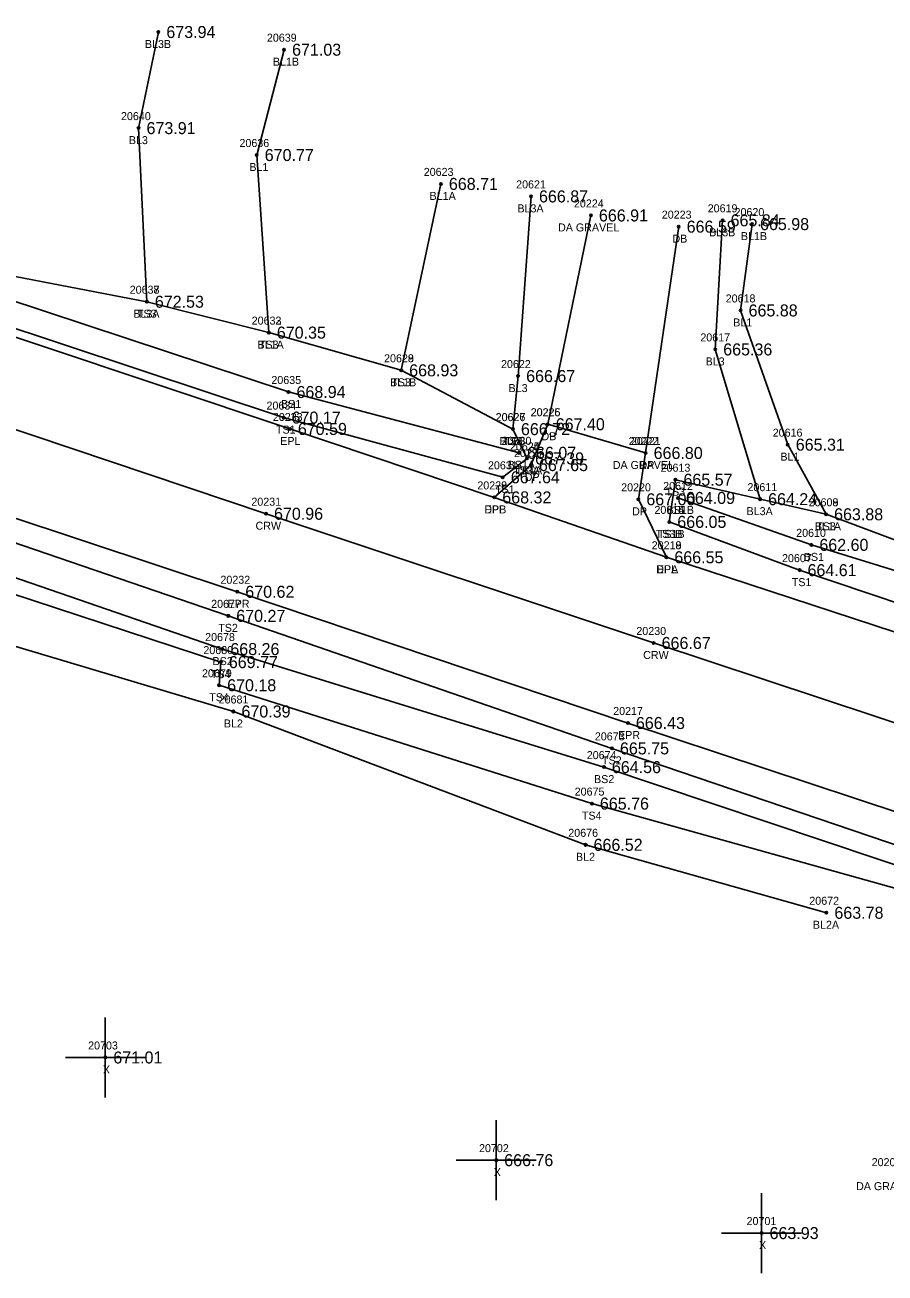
# Model space of a CAD drawing. Extents: x 1655675 to 1657082, y 1004080 to 1005193.
# Drawn here: x 1656108 to 1656215.6, y 1004608.6 to 1004764.5 of the extents above; entities that cross this region are included whole.
import ezdxf

# ---------------------------------------------------------------- set-up
doc = ezdxf.new("R2010")
doc.units = 0
for name, color, linetype in [('RD_DTM_BkLn1', 7, 'Continuous'), ('RD_DTM_BkLn2', 7, 'Continuous'), ('RD_DTM_BkLn_txCode', 7, 'Continuous'), ('RD_EX_Driveway', 7, 'Continuous'), ('RD_EX_Driveway_txCode', 7, 'Continuous'), ('RD_EX_Misc', 7, 'Continuous'), ('RD_EX_Misc_txCode', 7, 'Continuous'), ('RD_EX_Road', 7, 'Continuous'), ('RD_EX_Road_txCode', 7, 'Continuous'), ('RD_EX_TX_Driveway_ELEV', 7, 'Continuous'), ('RD_EX_TX_Misc_ELEV', 7, 'Continuous'), ('RD_EX_TX_Road_ELEV', 7, 'Continuous'), ('RD_HC_Survey_ELEV', 7, 'Continuous'), ('RD_HC_Survey_txCode', 7, 'Continuous'), ('RD_SMD_Locator', 7, 'Continuous')]:
    doc.layers.add(name, color=color, linetype=linetype)

msp = doc.modelspace()

# ---------------------------------------------------------------- linework, layer by layer
at = {"layer": 'RD_DTM_BkLn1'}
msp.add_line((1656160.04, 1004744.68), (1656155.08, 1004721.39), dxfattribs=at)
for points in [[(1656361.94, 1004629.69), (1656332.67, 1004639.45), (1656283.94, 1004655.24), (1656235.41, 1004671.18), (1656186.64, 1004687.32), (1656138.18, 1004703.47), (1656089.58, 1004719.78), (1656041.19, 1004735.88), (1655992.79, 1004752.04), (1655944.27, 1004768.13), (1655895.76, 1004783.85), (1655847.16, 1004799.72), (1655798.63, 1004815.7), (1655750.32, 1004831.65), (1655701.73, 1004847.83)], [(1656123.28, 1004729.96), (1656122.24, 1004751.65), (1656124.72, 1004763.66)], [(1656138.53, 1004726.1), (1656137.02, 1004748.29), (1656140.44, 1004761.45)], [(1656171.31, 1004743.12), (1656169.7, 1004720.67), (1656169.05, 1004714.04)], [(1656199.95, 1004705.29), (1656194.34, 1004724), (1656195.26, 1004740.13)], [(1656208.2, 1004703.4), (1656203.41, 1004712.1), (1656197.51, 1004728.87), (1656198.94, 1004739.66)], [(1656208.24, 1004653.61), (1656178.13, 1004662.1), (1656134.11, 1004678.76), (1656083.7, 1004693.78)]]:
    msp.add_lwpolyline(points, dxfattribs=at)
at = {"layer": 'RD_DTM_BkLn2'}
for points in [[(1656169.82, 1004711.08), (1656140.99, 1004718.68), (1656095.33, 1004733.78), (1656045.66, 1004750.66), (1655997.73, 1004765.48), (1655948.28, 1004782.13), (1655899.82, 1004798.93), (1655851.52, 1004814.56), (1655803.57, 1004832.22), (1655755.82, 1004847.44), (1655708.15, 1004866.52)], [(1656170.81, 1004710.38), (1656169.05, 1004714.04), (1656155.08, 1004721.39), (1656138.53, 1004726.1), (1656123.28, 1004729.96), (1656095.95, 1004735.19), (1656083.94, 1004739.91), (1656074.75, 1004751.62), (1656052.43, 1004759.33), (1656035.39, 1004767.92), (1656020.14, 1004775.42), (1656002.81, 1004778.08), (1655951.09, 1004790.04), (1655900.95, 1004804.56), (1655853.02, 1004819.57), (1655824.47, 1004830.21), (1655817.95, 1004830.44), (1655804.69, 1004834.86), (1655792.72, 1004842.88), (1655757.63, 1004852.03), (1655728.3, 1004865.14)], [(1656170.81, 1004710.38), (1656167.78, 1004708.02), (1656140.38, 1004715.48), (1656094.47, 1004730.71), (1656044.88, 1004747.29), (1655996.79, 1004763.35), (1655947.9, 1004779.96), (1655899.03, 1004795.71), (1655850.53, 1004811.22), (1655801.91, 1004828.51), (1655755.02, 1004844.41), (1655705.18, 1004859.33)], [(1656222.54, 1004657.66), (1656222.26, 1004660.26), (1656181.43, 1004674.15), (1656133.46, 1004690.71), (1656084.98, 1004707.29), (1656036.97, 1004722.43), (1655988.18, 1004739.61), (1655939.2, 1004755.93), (1655936.75, 1004753.71)], [(1656222.54, 1004657.66), (1656220.66, 1004655.59), (1656178.92, 1004667.25), (1656132.32, 1004682.04), (1656132.53, 1004684.93), (1656082.65, 1004701.3), (1656035.3, 1004716.15), (1655986.64, 1004734.85), (1655937.74, 1004750.26), (1655936.75, 1004753.71)], [(1656221.55, 1004658), (1656180.42, 1004671.81), (1656132.72, 1004686.56), (1656083.54, 1004703.49), (1656035.97, 1004719.09), (1655987.33, 1004737.77), (1655937.99, 1004752.87)], [(1656286.11, 1004675.22), (1656281.75, 1004677.92), (1656241.44, 1004690.96), (1656208.2, 1004703.4), (1656189.37, 1004707.72), (1656188.6, 1004702.45)], [(1656284.05, 1004674.96), (1656280.66, 1004674.21), (1656240.41, 1004689.08), (1656206.36, 1004699.58), (1656189.68, 1004705.44)], [(1656284.42, 1004671.89), (1656280.04, 1004671.54), (1656239.79, 1004684.68), (1656204.88, 1004696.42), (1656188.6, 1004702.45)]]:
    msp.add_lwpolyline(points, dxfattribs=at)
at = {"layer": 'RD_EX_Driveway'}
for p, q in [((1656178.8, 1004740.74), (1656173.4, 1004714.65)), ((1656185.64, 1004711.06), (1656189.77, 1004739.34))]:
    msp.add_line(p, q, dxfattribs=at)
msp.add_lwpolyline([(1656188.23, 1004698.03), (1656184.73, 1004705.27), (1656185.64, 1004711.06), (1656173.4, 1004714.65), (1656171.3, 1004709.55), (1656166.72, 1004705.51)], dxfattribs=at)
at = {"layer": 'RD_EX_Misc'}
for p, q in [((1656118.09, 1004630.53), (1656118.09, 1004640.53)), ((1656113.09, 1004635.53), (1656123.09, 1004635.53)), ((1656166.96, 1004617.7), (1656166.96, 1004627.7)), ((1656161.96, 1004622.7), (1656171.96, 1004622.7)), ((1656200.13, 1004608.59), (1656200.13, 1004618.59)), ((1656195.13, 1004613.59), (1656205.13, 1004613.59))]:
    msp.add_line(p, q, dxfattribs=at)
at = {"layer": 'RD_EX_Road'}
for points in [[(1656365.12, 1004639.99), (1656336.04, 1004649.34), (1656302.55, 1004660.37), (1656279.15, 1004668.23), (1656240.07, 1004681.05), (1656188.23, 1004698.03), (1656166.72, 1004705.51), (1656141.16, 1004714.06), (1656093.11, 1004730.11), (1656044.16, 1004746.75), (1655996.36, 1004762.45), (1655947.2, 1004778.68), (1655899.09, 1004794.03), (1655850.62, 1004809.99), (1655801.91, 1004826.1), (1655753.09, 1004842.31), (1655704.25, 1004858.1)], [(1656358.5, 1004619.83), (1656328.78, 1004629.48), (1656280.77, 1004645.39), (1656247.66, 1004656.11), (1656244.5, 1004656.52), (1656222.03, 1004663.57), (1656217.65, 1004665.96), (1656183.42, 1004677.32), (1656134.59, 1004693.72), (1656086.19, 1004709.75), (1656037.58, 1004726.13), (1655989.57, 1004741.99), (1655940.62, 1004757.88), (1655892.37, 1004773.61), (1655843.48, 1004789.36), (1655805.73, 1004801.4), (1655779.22, 1004810.43), (1655768.8, 1004813.1), (1655744.59, 1004822.13), (1655698.83, 1004837.65)]]:
    msp.add_lwpolyline(points, dxfattribs=at)
at = {"layer": 'RD_SMD_Locator'}
for centre in [(1656124.72, 1004763.66), (1656140.44, 1004761.45), (1656122.24, 1004751.65), (1656137.02, 1004748.29), (1656160.04, 1004744.68), (1656171.31, 1004743.12), (1656178.8, 1004740.74), (1656195.26, 1004740.13), (1656189.77, 1004739.34), (1656198.94, 1004739.66), (1656123.28, 1004729.96), (1656123.28, 1004729.96), (1656197.51, 1004728.87), (1656138.53, 1004726.1), (1656138.53, 1004726.1), (1656194.34, 1004724), (1656155.08, 1004721.39), (1656155.08, 1004721.39), (1656169.7, 1004720.67), (1656140.99, 1004718.68), (1656140.38, 1004715.48), (1656141.16, 1004714.06), (1656169.05, 1004714.04), (1656169.05, 1004714.04), (1656173.4, 1004714.65), (1656173.4, 1004714.65), (1656203.41, 1004712.1), (1656169.82, 1004711.08), (1656185.64, 1004711.06), (1656185.64, 1004711.06), (1656170.81, 1004710.38), (1656170.81, 1004710.38), (1656171.3, 1004709.55), (1656167.78, 1004708.02), (1656189.37, 1004707.72), (1656166.72, 1004705.51), (1656166.72, 1004705.51), (1656184.73, 1004705.27), (1656189.68, 1004705.44), (1656199.95, 1004705.29), (1656138.18, 1004703.47), (1656208.2, 1004703.4), (1656208.2, 1004703.4), (1656188.6, 1004702.45), (1656188.6, 1004702.45), (1656206.36, 1004699.58), (1656188.23, 1004698.03), (1656188.23, 1004698.03), (1656204.88, 1004696.42), (1656134.59, 1004693.72), (1656133.46, 1004690.71), (1656186.64, 1004687.32), (1656132.72, 1004686.56), (1656132.53, 1004684.93), (1656132.32, 1004682.04), (1656134.11, 1004678.76), (1656183.42, 1004677.32), (1656181.43, 1004674.15), (1656180.42, 1004671.81), (1656178.92, 1004667.25), (1656178.13, 1004662.1), (1656208.24, 1004653.61), (1656118.09, 1004635.53), (1656166.96, 1004622.7), (1656200.13, 1004613.59)]:
    msp.add_circle(centre, 0.15, dxfattribs=at)

# ---------------------------------------------------------------- texts
at = {"layer": 'RD_DTM_BkLn_txCode'}
for s, p in [('BL3B', (1656123.04, 1004761.66)), ('20639', (1656138.29, 1004762.45)), ('BL1B', (1656139.04, 1004759.45)), ('20640', (1656120.05, 1004752.65)), ('BL3', (1656121.03, 1004749.65)), ('20636', (1656134.86, 1004749.29)), ('BL1', (1656136.1, 1004746.29)), ('20623', (1656157.9, 1004745.68)), ('20621', (1656169.45, 1004744.12)), ('BL1A', (1656158.63, 1004742.68)), ('BL3A', (1656169.61, 1004741.12)), ('20619', (1656193.4, 1004741.13)), ('20620', (1656196.76, 1004740.66)), ('BL3B', (1656193.58, 1004738.13)), ('BL1B', (1656197.55, 1004737.66)), ('20637', (1656121.14, 1004730.96)), ('20638', (1656121.14, 1004730.96)), ('20618', (1656195.65, 1004729.87)), ('BL3A', (1656121.59, 1004727.96)), ('TS3', (1656122.04, 1004727.96)), ('20632', (1656136.39, 1004727.1)), ('20633', (1656136.39, 1004727.1)), ('BL1', (1656196.59, 1004726.87)), ('BL1A', (1656137.12, 1004724.1)), ('TS3', (1656137.29, 1004724.1)), ('20617', (1656192.48, 1004725)), ('20628', (1656152.94, 1004722.39)), ('20629', (1656152.94, 1004722.39)), ('20622', (1656167.56, 1004721.67)), ('BL3', (1656193.14, 1004722)), ('20635', (1656138.85, 1004719.68)), ('BL1B', (1656153.69, 1004719.39)), ('TS3', (1656153.84, 1004719.39)), ('BL3', (1656168.5, 1004718.67)), ('20634', (1656138.24, 1004716.48)), ('BS1', (1656140.05, 1004716.68)), ('20626', (1656166.88, 1004715.04)), ('20627', (1656166.9, 1004715.04)), ('TS1', (1656139.42, 1004713.48)), ('20616', (1656201.53, 1004713.1)), ('BL3B', (1656167.37, 1004712.04)), ('20630', (1656167.64, 1004712.08)), ('TS3', (1656167.8, 1004712.04)), ('20624', (1656168.67, 1004711.38)), ('20625', (1656168.67, 1004711.38)), ('BL1', (1656202.49, 1004710.1)), ('20631', (1656165.93, 1004709.02)), ('BS1A', (1656168.39, 1004709.08)), ('TS3A', (1656169.08, 1004708.38)), ('TS1A', (1656169.36, 1004708.38)), ('20613', (1656187.51, 1004708.72)), ('TS1', (1656166.82, 1004706.02)), ('20612', (1656187.83, 1004706.44)), ('TS3', (1656188.13, 1004705.72)), ('20611', (1656198.37, 1004706.29)), ('20614', (1656186.74, 1004703.45)), ('20615', (1656186.74, 1004703.45)), ('BS1B', (1656188.27, 1004703.44)), ('20608', (1656206.02, 1004704.4)), ('20609', (1656206.02, 1004704.4)), ('BL3A', (1656198.26, 1004703.29)), ('TS3B', (1656186.89, 1004700.45)), ('TS1B', (1656187.17, 1004700.45)), ('20610', (1656204.46, 1004700.58)), ('BL1A', (1656206.79, 1004701.4)), ('TS3', (1656206.96, 1004701.4)), ('20607', (1656202.69, 1004697.42)), ('BS1', (1656205.41, 1004697.58)), ('TS1', (1656203.91, 1004694.42)), ('20677', (1656131.32, 1004691.71)), ('TS2', (1656132.21, 1004688.71)), ('20678', (1656130.57, 1004687.56)), ('20680', (1656130.35, 1004685.93)), ('BS2', (1656131.49, 1004684.56)), ('20679', (1656130.18, 1004683.04)), ('TS4', (1656131.29, 1004682.93)), ('TS4', (1656131.08, 1004680.04)), ('20681', (1656132.26, 1004679.76)), ('BL2', (1656132.91, 1004676.76)), ('20673', (1656179.29, 1004675.15)), ('20674', (1656178.28, 1004672.81)), ('TS2', (1656180.19, 1004672.15)), ('BS2', (1656179.19, 1004669.81)), ('20675', (1656176.77, 1004668.25)), ('TS4', (1656177.67, 1004665.25)), ('20676', (1656175.97, 1004663.1)), ('BL2', (1656176.93, 1004660.1)), ('20672', (1656206.1, 1004654.61)), ('BL2A', (1656206.55, 1004651.61))]:
    msp.add_text(s, height=1, dxfattribs=at).set_placement(p)
at = {"layer": 'RD_EX_Driveway_txCode'}
for s, p in [('20224', (1656176.68, 1004741.74)), ('20223', (1656187.66, 1004740.34)), ('DA GRAVEL', (1656174.69, 1004738.74)), ('DB', (1656188.99, 1004737.34)), ('20226', (1656171.26, 1004715.65)), ('20225', (1656171.28, 1004715.65)), ('DB', (1656172.62, 1004712.65)), ('DP', (1656172.62, 1004712.65)), ('20222', (1656183.52, 1004712.06)), ('20221', (1656183.8, 1004712.06)), ('20227', (1656169.18, 1004710.55)), ('DA GRAVEL', (1656181.53, 1004709.06)), ('DP', (1656184.86, 1004709.06)), ('20228', (1656164.6, 1004706.51)), ('DP', (1656170.52, 1004707.55)), ('20220', (1656182.58, 1004706.27)), ('DPB', (1656165.47, 1004703.51)), ('DP', (1656183.95, 1004703.27)), ('20219', (1656186.4, 1004699.03)), ('DPA', (1656186.97, 1004696.03)), ('20209', (1656213.9, 1004621.95)), ('DA GRAVEL', (1656211.95, 1004618.95))]:
    msp.add_text(s, height=1, dxfattribs=at).set_placement(p)
at = {"layer": 'RD_EX_Misc_txCode'}
for s, p in [('20703', (1656115.94, 1004636.53)), ('X', (1656117.78, 1004633.53)), ('20702', (1656164.81, 1004623.7)), ('X', (1656166.65, 1004620.7)), ('20701', (1656198.26, 1004614.59)), ('X', (1656199.82, 1004611.59))]:
    msp.add_text(s, height=1, dxfattribs=at).set_placement(p)
at = {"layer": 'RD_EX_Road_txCode'}
for s, p in [('20233', (1656139.04, 1004715.06)), ('EPL', (1656139.96, 1004712.06)), ('20229', (1656164.6, 1004706.51)), ('EPL', (1656165.51, 1004703.51)), ('20218', (1656186.4, 1004699.03)), ('EPL', (1656187.03, 1004696.03)), ('20232', (1656132.48, 1004694.72)), ('EPR', (1656133.37, 1004691.72)), ('20217', (1656181.58, 1004678.32)), ('EPR', (1656182.19, 1004675.32))]:
    msp.add_text(s, height=1, dxfattribs=at).set_placement(p)
at = {"layer": 'RD_EX_TX_Driveway_ELEV'}
for s, p in [('666.91', (1656179.8, 1004739.99)), ('666.59', (1656190.77, 1004738.59)), ('667.40', (1656174.4, 1004713.9)), ('667.40', (1656174.4, 1004713.9)), ('666.80', (1656186.64, 1004710.31)), ('666.80', (1656186.64, 1004710.31)), ('667.65', (1656172.3, 1004708.8)), ('668.32', (1656167.72, 1004704.76)), ('667.00', (1656185.73, 1004704.52)), ('666.55', (1656189.23, 1004697.28))]:
    msp.add_text(s, height=1.5, dxfattribs=at).set_placement(p)
at = {"layer": 'RD_EX_TX_Misc_ELEV'}
for s, p in [('673.94', (1656125.72, 1004762.91)), ('671.03', (1656141.44, 1004760.7)), ('673.91', (1656123.24, 1004750.9)), ('670.77', (1656138.02, 1004747.54)), ('668.71', (1656161.04, 1004743.93)), ('666.87', (1656172.31, 1004742.37)), ('665.84', (1656196.26, 1004739.38)), ('665.98', (1656199.94, 1004738.91)), ('672.53', (1656124.28, 1004729.21)), ('672.53', (1656124.28, 1004729.21)), ('665.88', (1656198.51, 1004728.12)), ('670.35', (1656139.53, 1004725.35)), ('670.35', (1656139.53, 1004725.35)), ('665.36', (1656195.34, 1004723.25)), ('668.93', (1656156.08, 1004720.64)), ('668.93', (1656156.08, 1004720.64)), ('666.67', (1656170.7, 1004719.92)), ('668.94', (1656141.99, 1004717.93)), ('670.17', (1656141.38, 1004714.73)), ('666.72', (1656170.05, 1004713.29)), ('666.72', (1656170.05, 1004713.29)), ('665.31', (1656204.41, 1004711.35)), ('666.07', (1656170.82, 1004710.33)), ('667.39', (1656171.81, 1004709.63)), ('667.39', (1656171.81, 1004709.63)), ('667.64', (1656168.78, 1004707.27)), ('665.57', (1656190.37, 1004706.97)), ('664.09', (1656190.68, 1004704.69)), ('664.24', (1656200.95, 1004704.54)), ('666.05', (1656189.6, 1004701.7)), ('666.05', (1656189.6, 1004701.7)), ('663.88', (1656209.2, 1004702.65)), ('663.88', (1656209.2, 1004702.65)), ('662.60', (1656207.36, 1004698.83)), ('664.61', (1656205.88, 1004695.67)), ('670.27', (1656134.46, 1004689.96)), ('668.26', (1656133.72, 1004685.81)), ('669.77', (1656133.53, 1004684.18)), ('670.18', (1656133.32, 1004681.29)), ('670.39', (1656135.11, 1004678.01)), ('665.75', (1656182.43, 1004673.4)), ('664.56', (1656181.42, 1004671.06)), ('665.76', (1656179.92, 1004666.5)), ('666.52', (1656179.13, 1004661.35)), ('663.78', (1656209.24, 1004652.86)), ('671.01', (1656119.09, 1004634.78)), ('666.76', (1656167.96, 1004621.95)), ('663.93', (1656201.13, 1004612.84))]:
    msp.add_text(s, height=1.5, dxfattribs=at).set_placement(p)
at = {"layer": 'RD_EX_TX_Road_ELEV'}
for s, p in [('670.59', (1656142.16, 1004713.31)), ('668.32', (1656167.72, 1004704.76)), ('666.55', (1656189.23, 1004697.28)), ('670.62', (1656135.59, 1004692.97)), ('666.43', (1656184.42, 1004676.57))]:
    msp.add_text(s, height=1.5, dxfattribs=at).set_placement(p)
at = {"layer": 'RD_HC_Survey_ELEV'}
for s, p in [('670.96', (1656139.18, 1004702.72)), ('666.67', (1656187.64, 1004686.57))]:
    msp.add_text(s, height=1.5, dxfattribs=at).set_placement(p)
at = {"layer": 'RD_HC_Survey_txCode'}
for s, p in [('20231', (1656136.35, 1004704.47)), ('CRW', (1656136.87, 1004701.47)), ('20230', (1656184.48, 1004688.32)), ('CRW', (1656185.33, 1004685.32))]:
    msp.add_text(s, height=1, dxfattribs=at).set_placement(p)

doc.saveas('drawing.dxf')
